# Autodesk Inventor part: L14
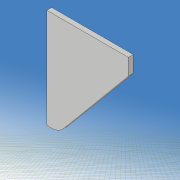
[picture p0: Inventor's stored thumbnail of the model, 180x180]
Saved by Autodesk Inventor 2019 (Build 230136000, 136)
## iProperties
Created: 2021-05
Part Number: L14
Material: 一般
Document SubType Name: Modeling
Designer: kikut
Density: 1 g/cm^3
Appearance: 既定
Mass: 0.00934248 g
Surface Area: 0.426451 cm^2
Volume: 0.00934248 cm^3
Author: kikut
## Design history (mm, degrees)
sketch "スケッチ1"
  geometry: L1 (80, 60)-(-80, 60); L2 (-80, 60)-(-80, -60); L3 (-80, -60)-(80, -60); L4 (80, -60)-(80, 60); L5 (80, 60)-(-80, -60); L6 (-80, 60)-(80, -60); 1 further point
  constraints: 12 end point, 2 midpoint, 2 parallel, 1 horizontal, 1 perpendicular
  dimensions: "d0" = 160 distance of L2.end L3.end; "d1" = 120 distance of L1.end L2.end
extrude "押し出し1" new body sketch "スケッチ1" stored distance "d2" = 0.6; taper "d3" = 0 deg
sketch "スケッチ2"
  geometry: L1 (-140, 0)-(140, 0) reference; L2 (0, -54)-(20, -30); L3 (0, 54)-(20, 30); L4 (0, -3)-(6.514, -3); L5 (6.514, -3)-(16, -6); L6 (16, -6)-(24, -3); L7 (24, -3)-(33.716, -3); L8 (0, 3)-(6.514, 3); L9 (6.514, 3)-(16, 6); L10 (16, 6)-(24, 3); L11 (24, 3)-(33.716, 3); L12 (0, -98)-(0, 98) reference; L13 (-100, -70)-(100, -70); L14 (100, -70)-(100, 70); L15 (100, 70)-(-100, 70); L16 (-100, 70)-(-100, -70); L17 (-100, -70)-(100, 70); L18 (100, -70)-(-100, 70); A1 r 60 centre (54.312, 28.5) between (0, 54) and (0, 3); A2 r 60 centre (54.312, -28.5) between (0, -3) and (0, -54); A3 r 18.111 centre (18, -12) between (20, -30) and (33.716, -3); A4 r 18.111 centre (18, 12) between (33.716, 3) and (20, 30); 1 further point
  constraints: 32 end point, 8 point on circle, 8 symmetric about line, 4 centre point, 3 horizontal, 2 collinear, 2 midpoint, 2 parallel, 1 perpendicular
  dimensions: "d5" = 60 radius of A1; "d6" = 6 distance of L8.start L4.start; "d7" = 108 distance of L3.start L2.start; "d8" = 0 horizontal distance of L3.start L8.start; "d9" = 60 distance of L3.end L2.end; "d10" = 0 horizontal distance of point (0, 0) L3.start; "d11" = 20 horizontal distance of L3.start L3.end; "d12" = 24 distance of A4.centre A3.centre; "d13" = 6 distance of L11.end L7.end; "d14" = 12 distance of L9.end L5.end; "d15" = 16 distance from line of L12 L5.end; "d16" = 24 distance from line of L6.end L12; "d17" = 200 distance of L14.end L15.end; "d18" = 140 distance of L15.end L13.start; "d30" = 18 distance from line of L12 A4.centre
extrude "押し出し2" cut sketch "スケッチ2" stored distance "d19" = 10; taper "d20" = 0 deg
sketch "スケッチ3"
  geometry: L1 (49.705, -17.97)-(33.948, -15.191); L2 (33.948, -15.191)-(34.295, -13.222); L3 (34.295, -13.222)-(50.052, -16); L4 (50.052, -16)-(49.705, -17.97); L5 (49.705, -17.97)-(34.295, -13.222); L6 (33.948, -15.191)-(50.052, -16); L7 (50.052, 16)-(34.295, 13.222); L8 (34.295, 13.222)-(33.948, 15.191); L9 (33.948, 15.191)-(49.705, 17.97); L10 (49.705, 17.97)-(50.052, 16); L11 (50.052, 16)-(33.948, 15.191); L12 (34.295, 13.222)-(49.705, 17.97); L13 (-112, 0)-(112, 0) reference; L14 (0, -84)-(0, 84) reference; 3 further points
  constraints: 24 end point, 4 midpoint, 4 parallel, 2 perpendicular, 2 symmetric about line
  dimensions: "d21" = 2 distance of L3.end L1.start; "d22" = 2 distance of L9.end L7.start; "d23" = 16 distance of L8.end L9.end; "d24" = 42 distance from line of L14 point (42, 15.596); "d26" = 10 deg angle of L7 L13; "d62" = 16 distance from line of L3.end L13
extrude "押し出し3" join sketch "スケッチ3" distance "d27" = 0.6; taper "d28" = 0 deg
fillet "フィレット1" dims "d31" = 2
fillet "フィレット2" dims "d32" = 1
sketch "スケッチ7"
  geometry: L1 (-20, 60)-(80, 60); L2 (80, 60)-(80, -60); L3 (80, -60)-(-20, -60); L4 (-20, -60)-(-20, 60); L5 (0, -82.207)-(0, 85.793) reference; L6 (-40, 0)-(100, 0) reference; L7 (0, -40)-(10, -40); L8 (10, -40)-(10, -56); L9 (10, -56)-(0, -56); L10 (0, -56)-(0, -40); 1 further point
  constraints: 16 end point, 4 parallel, 2 horizontal, 2 perpendicular, 1 other
  dimensions: "d80" = 120 distance of L3.end L1.start; "d81" = 20 distance between parallel lines of L5 L4; "d82" = 100 distance of L1.start L1.end; "d84" = 10 distance of L8.end L9.end; "d85" = 16 distance of L7.end L8.end; "d86" = 20 distance between parallel lines of L4 L10; "d90" = 40 distance between parallel lines of L7 L6
extrude "押し出し5" cut sketch "スケッチ7" stored distance "d87" = 10; taper "d88" = 0 deg
node "ソリッド1"
